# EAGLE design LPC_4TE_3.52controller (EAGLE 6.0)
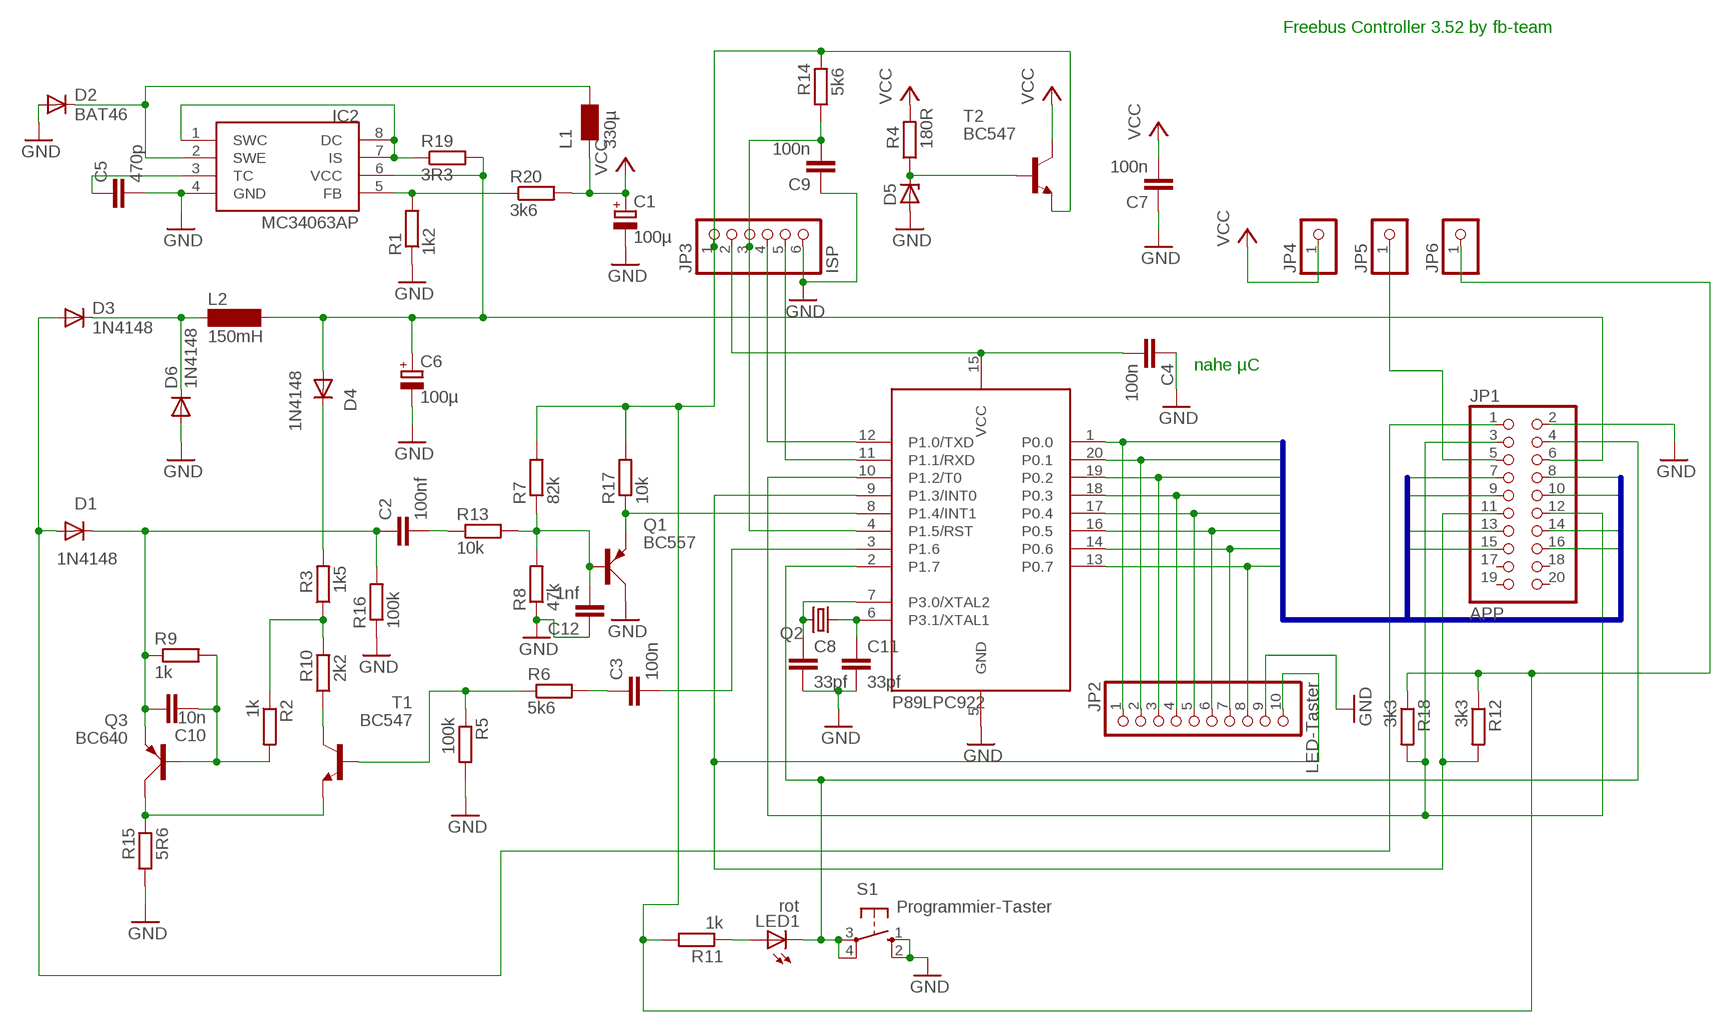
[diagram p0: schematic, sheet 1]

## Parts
C1  100µ  CPOL-EUE5-8.5  [E5-8,5]
C2  100nf  C-EU050-024X044  [C050-024X044]
C3  100n  C-EU050-024X044  [C050-024X044]
C4  100n  C-EU050-024X044  [C050-024X044]
C5  470p  C-EU025-024X044  [C025-024X044]
C6  100µ  CPOL-EUE5-8.5  [E5-8,5]
C7  100n  C-EU050-024X044  [C050-024X044]
C8  33pf  C-EUC1206  [C1206]
C9  100n  C-EU050-024X044  [C050-024X044]
C10  10n  C-EU050-024X044  [C050-024X044]
C11  33pf  C-EUC1206  [C1206]
C12  1nf  C-EU050-024X044  [C050-024X044]
D1  1N4148  1N4148DO35-7  [DO35-7]
D2  BAT46  DIODE-C1702-05  [C1702-05]
D3  1N4148  DIODE-D-2.5  [D-2.5]
D4  1N4148  1N4148DO35-10  [DO35-10]
D5  BZX85ZD-VL  [RAD2,5L]
D6  1N4148  DIODE-D-2.5  [D-2.5]
IC1  89LPC922FN  89LPC922  [DIL20]
IC2  MC34063AP  [DIL08]
JP1  APP  PINHD-2X10  [2X10]
JP2  LED-Taster  PINHD-1X10  [1X10]
JP3  ISP  PINHD-1X6  [1X06]
JP4  PINHD-1X1  [1X01]
JP5  PINHD-1X1  [1X01]
JP6  PINHD-1X1  [1X01]
L1  330µ  L_R85  [L_RAD_D8RM5]
L2  150mH  SD12-1000  [SD12_1000]
LED1  rot  LED3MM  [LED3MM]
Q1  BC557  [SOT54A]
Q2  CRYSTALHC49U70  [HC49U70]
Q3  BC640  [SOT54D]
R1  1k2  R-EU_0207/10  [0207/10]
R2  1k  R-EU_0207/7  [0207/7]
R3  1k5  R-EU_0207/7  [0207/7]
R4  180R  R-EU_0207/2V  [0207/2V]
R5  100k  R-EU_0207/2V  [0207/2V]
R6  5k6  R-EU_0207/7  [0207/7]
R7  82k  R-EU_0207/7  [0207/7]
R8  47k  R-EU_0207/7  [0207/7]
R9  1k  R-EU_0207/7  [0207/7]
R10  2k2  R-EU_0207/7  [0207/7]
R11  1k  R-EU_0207/10  [0207/10]
R12  3k3  R-EU_0207/10  [0207/10]
R13  10k  R-EU_0207/7  [0207/7]
R14  5k6  R-EU_0207/10  [0207/10]
R15  5R6  R-EU_0207/2V  [0207/2V]
R16  100k  R-EU_0207/7  [0207/7]
R17  10k  R-EU_0207/7  [0207/7]
R18  3k3  R-EU_0207/10  [0207/10]
R19  3R3  R-EU_0207/10  [0207/10]
R20  3k6  R-EU_0207/10  [0207/10]
S1  Programmier-Taster  10-XX  [B3F-10XX]
T1  BC547  [TO92]
T2  BC547  [TO92]

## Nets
/RESTET: C9.2 IC1.4(P1.5/RST) JP3.3 R14.1
DRAIN: C2.1 C10.1 D1.C Q3.E R9.1 R16.2
EIB_DC: C6.+ D4.A IC2.6(VCC) JP1.6 L2.2 R19.2
EIBIN: IC1.8(P1.4/INT1) Q1.E R17.1
GND: C1.- C4.1 C5.2 C6.- C7.1 C8.2 C9.1 C11.2 C12.1 D2.A D5.A D6.A IC1.5(GND) IC2.4(GND) JP1.2 JP2.9 JP3.6 Q1.C R1.1 R5.2 R8.1 R15.1 R16.1 S1.1(S) S1.2(S1)
INT0_TASTER: IC1.9(P1.3/INT0) JP1.11 JP2.10 R12.2
N$1: C3.1 R6.2
N$2: C2.2 R13.1
N$3: IC2.5(FB) R1.2 R20.1
N$4: IC2.1(SWC) IC2.7(IS) IC2.8(DC) R19.1
N$5: C3.2 IC1.3(P1.6)
N$6: R10.1 T1.3(C)
N$7: Q3.C R15.2 T1.1(E)
N$8: D3.C D6.C L2.1
N$9: D4.C R3.2
N$10: D2.C IC2.2(SWE) L1.1
N$11: R2.1 R3.1 R10.2
N$12: R5.1 R6.1 T1.2(B)
N$13: C5.1 IC2.3(TC)
N$14: C12.2 Q1.B R7.1 R8.2 R13.2
N$15: C10.2 Q3.B R2.2 R9.2
N$16: D1.A D3.A JP1.1
N$17: C11.1 IC1.6(P3.1/XTAL1) Q2.1
N$18: D5.C R4.1 T2.2(B)
N$19: C8.1 IC1.7(P3.0/XTAL2) Q2.2
N$20: JP1.5 JP5.1
N$29: IC1.12(P1.0/TXD) JP3.4
N$30: IC1.11(P1.1/RXD) JP3.5
N$41: LED1.A R11.1
P0.0: IC1.1(P0.0) JP1.7 JP2.1
P0.1: IC1.20(P0.1) JP1.8 JP2.2
P0.2: IC1.19(P0.2) JP1.9 JP2.3
P0.3: IC1.18(P0.3) JP1.10 JP2.4
P0.4: IC1.17(P0.4) JP1.13 JP2.5
P0.5: IC1.16(P0.5) JP1.14 JP2.6
P0.6: IC1.14(P0.6) JP1.15 JP2.7
P0.7: IC1.13(P0.7) JP1.16 JP2.8
PROG: IC1.2(P1.7) JP1.4 LED1.K(C) S1.3(P) S1.4(P1)
PWM: IC1.10(P1.2/T0) JP1.3 JP1.12 R18.2
VCC: C1.+ C7.2 JP4.1 L1.2 R4.2 R20.2 T2.3(C)
VCC_3V3: JP3.1 JP6.1 R7.2 R11.2 R12.1 R14.2 R17.2 R18.1 T2.1(E)
VCC_LPC: C4.2 IC1.15(VCC) JP3.2
Unconnected: JP1.17 JP1.18 JP1.19 JP1.20

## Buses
P0.[0..7]

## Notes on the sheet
- Freebus Controller 3.52 by fb-team
- nahe µC
- P89LPC922

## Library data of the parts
C1 C6 = rcl:CPOL-EU: POLARIZED CAPACITOR, European symbol
C2-C5 C7-C12 = rcl:C-EU: CAPACITOR, European symbol
D1 D4 = diode:1N4148: DIODE
D2 D3 D6 = diode:DIODE-: DIODE
D5 = diode:BZX85: Z DIODE
IC1 = micro-philips:89LPC922
IC2 = mc34063:MC34063
JP1 = pinhead:PINHD-2X10: PIN HEADER
JP2 = pinhead:PINHD-1X10: PIN HEADER
JP3 = pinhead:PINHD-1X6: PIN HEADER
JP4-JP6 = pinhead:PINHD-1X1: PIN HEADER
L1 = fbctrls1:L
L2 = inductor-neosid:SD12: INDUCTOR
LED1 = led:LED: LED
Q1 = transistor-small-signal:BC557: PNP TRANSISTOR
Q2 = crystal:CRYSTAL: CRYSTAL
Q3 = transistor-small-signal:BC640: PNP TRANSISTOR
R1-R20 = rcl:R-EU_: RESISTOR, European symbol
S1 = switch-omron:10-XX: OMRON SWITCH
T1 T2 = transistor:BC547: NPN TRANSISTOR

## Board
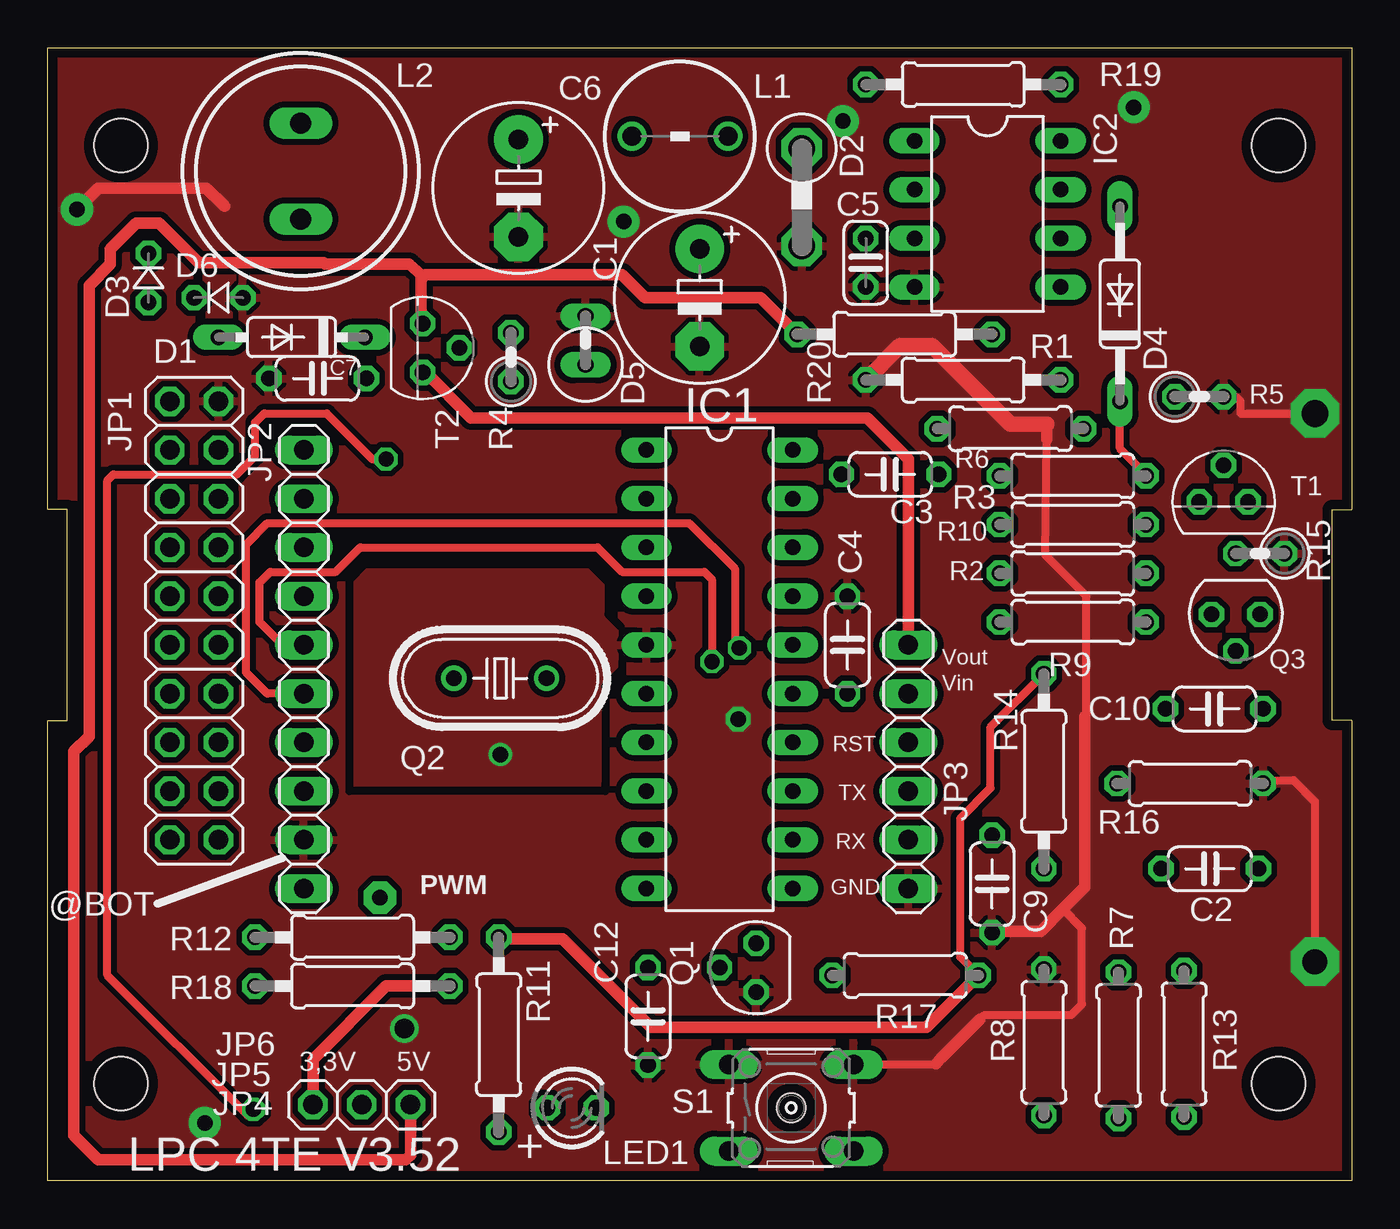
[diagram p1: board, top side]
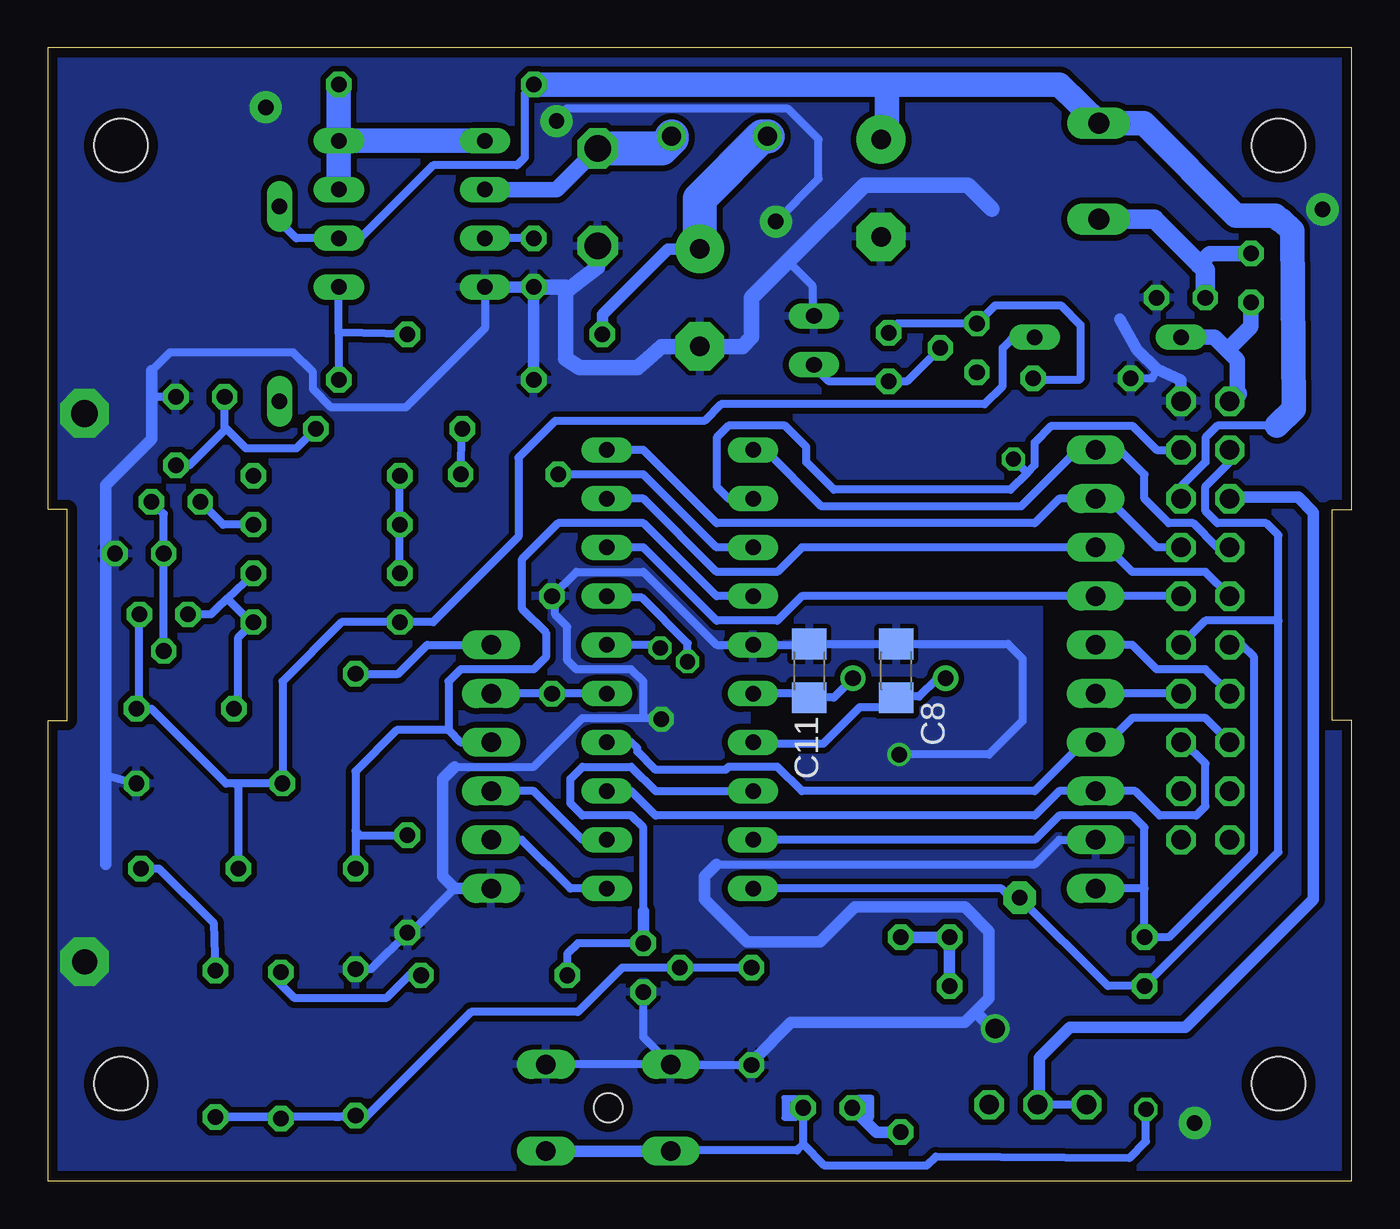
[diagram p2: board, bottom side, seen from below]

Size 67.94 x 59.05 mm. Coordinates in mm from the lower left corner, seen from the top.
Outline: 0,0 0,24 1,24 1,35 0,35 0,59.05 67.94,59.05 67.94,35 66.94,35 66.94,24 67.94,24 67.94,0 0,0
Copper layers (1*16): Top 0.035mm / dielectric 1.5mm / Bottom 0.035mm
Design rules "default *": minimum track width 10mil, minimum drill 24mil, track to track 12mil, track to pad 12mil, pad to pad 12mil, via to via 12mil, smd to smd 8mil, copper to edge 20mil, drill to drill 8mil, minimum pad ring 10mil, minimum via ring 8mil, stop-mask expansion 4mil, vias tented up to drill 0mil, thermal gap 10mil
Holes 2.8 mm at 3.81,53.98 64.14,53.98 64.14,5.08 3.81,5.08
Holes 1.5 mm at 38.73,3.81
tRestrict: 11 lines
bRestrict: 3 lines

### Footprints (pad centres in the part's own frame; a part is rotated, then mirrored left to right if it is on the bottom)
E5-8,5 = drill 1.016 pad 2.54 round: + -2.54,0 | drill 1.016 pad 2.54 octagon: - 2.54,0
C050-024X044 = drill 0.813 octagon: 1 -2.54,0; 2 2.54,0
C025-024X044 = drill 0.813 octagon: 1 -1.27,0; 2 1.27,0
C1206 = smd 1.6 x 1.8: 1 -1.4,0; 2 1.4,0
DO35-7 = drill 0.813 long: A 3.81,0; C -3.81,0
C1702-05 = drill 1.397 octagon: A 2.54,0; C -2.54,0
D-2.5 = drill 0.813 octagon: A 1.27,0; C -1.27,0
DO35-10 = drill 0.813 long: A 5.08,0; C -5.08,0
RAD2,5L = drill 0.813 long: A 1.27,0; C -1.27,0
DIL20 = drill 0.813 long: 1 -11.43,-3.81; 2 -8.89,-3.81; 3 -6.35,-3.81; 4 -3.81,-3.81; 5 -1.27,-3.81; 6 1.27,-3.81; 7 3.81,-3.81; 8 6.35,-3.81; 9 8.89,-3.81; 10 11.43,-3.81; 11 11.43,3.81; 12 8.89,3.81; 13 6.35,3.81; 14 3.81,3.81; 15 1.27,3.81; 16 -1.27,3.81; 17 -3.81,3.81; 18 -6.35,3.81; 19 -8.89,3.81; 20 -11.43,3.81
DIL08 = drill 0.813 long: 1 -3.81,-3.81; 2 -1.27,-3.81; 3 1.27,-3.81; 4 3.81,-3.81; 5 3.81,3.81; 6 1.27,3.81; 7 -1.27,3.81; 8 -3.81,3.81
2X10 = drill 1.016 octagon: 1 -11.43,-1.27; 2 -11.43,1.27; 3 -8.89,-1.27; 4 -8.89,1.27; 5 -6.35,-1.27; 6 -6.35,1.27; 7 -3.81,-1.27; 8 -3.81,1.27; 9 -1.27,-1.27; 10 -1.27,1.27; 11 1.27,-1.27; 12 1.27,1.27; 13 3.81,-1.27; 14 3.81,1.27; 15 6.35,-1.27; 16 6.35,1.27; 17 8.89,-1.27; 18 8.89,1.27; 19 11.43,-1.27; 20 11.43,1.27
1X10 = drill 1.016 long: 1 -11.43,0; 2 -8.89,0; 3 -6.35,0; 4 -3.81,0; 5 -1.27,0; 6 1.27,0; 7 3.81,0; 8 6.35,0; 9 8.89,0; 10 11.43,0
1X06 = drill 1.016 long: 1 -6.35,0; 2 -3.81,0; 3 -1.27,0; 4 1.27,0; 5 3.81,0; 6 6.35,0
1X01 = drill 1.016 octagon: 1 0,0
L_RAD_D8RM5 = drill 1 round: 1 -2.5,0; 2 2.5,0
SD12_1000 = drill 1.1 long: 1 -2.5,0; 2 2.5,0
LED3MM = drill 0.813 octagon: A -1.27,0; K 1.27,0
SOT54A = drill 0.813 octagon: B 0,1.905; C -1.27,0; E 1.27,0
HC49U70 = drill 0.813 round: 1 -2.413,0; 2 2.413,0
SOT54D = drill 0.813 octagon: B 1.27,0; C 0,1.905; E -1.27,0
0207/10 = drill 0.813 octagon: 1 -5.08,0; 2 5.08,0
0207/7 = drill 0.813 octagon: 1 -3.81,0; 2 3.81,0
0207/2V = drill 0.813 octagon: 1 -1.27,0; 2 1.27,0
B3F-10XX = drill 1.016 long: 1 -3.251,2.261; 2 3.251,2.261; 3 -3.251,-2.261; 4 3.251,-2.261
TO92 = drill 0.813 octagon: 1 1.27,0; 2 0,1.905; 3 -1.27,0

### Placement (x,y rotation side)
C1  33.97,46.04 270 top
C2  60.56,16.27 0 top
C3  43.89,36.83 180 top
C4  41.67,27.94 270 top
C5  42.62,47.86 270 top
C6  24.53,51.75 270 top
C7  14.05,41.83 0 top
C8  23.73,26.59 90 bottom
C9  49.21,15.48 90 top
C10  60.8,24.61 180 top
C11  28.26,26.59 90 bottom
C12  31.27,8.57 90 top
D1  12.7,43.97 180 top
D2  39.29,51.28 270 top
D3  5.24,47.07 270 top
D4  55.88,45.72 90 top
D5  28.02,43.81 90 top
D6  8.89,46.04 0 top
IC1  35,26.67 270 top
IC2  48.97,50.4 270 top
JP1  7.62,29.21 270 top
JP2  13.34,26.67 270 top
JP3  44.85,21.59 270 top
JP4  18.89,3.97 0 top
JP5  16.35,3.97 0 top
JP6  13.81,3.97 0 top
L1  32.94,54.45 180 top
L2  13.18,52.63 90 top
LED1  27.3,3.81 0 top
Q1  36.91,11.11 90 top
Q2  23.57,26.19 180 top
Q3  61.91,29.53 180 top
R1  47.7,41.75 0 top
R2  53.42,31.67 0 top
R3  53.42,36.75 0 top
R4  24.13,42.94 90 top
R5  60.01,40.88 0 top
R6  50.16,39.21 180 top
R7  55.8,7.06 90 top
R8  51.91,7.22 270 top
R9  53.42,29.13 0 top
R10  53.42,34.21 180 top
R11  23.5,7.62 90 top
R12  15.88,12.7 180 top
R13  59.21,7.14 270 top
R14  51.91,21.35 90 top
R15  63.18,32.7 180 top
R16  59.53,20.72 180 top
R17  44.69,10.72 0 top
R18  15.88,10.16 180 top
R19  47.7,57.15 180 top
R20  44.13,44.13 180 top
S1  38.73,3.81 0 top
T1  61.28,35.4 0 top
T2  19.53,43.42 270 top

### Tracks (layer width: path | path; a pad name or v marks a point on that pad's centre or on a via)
/RESTET
  Bottom 0.406: IC1.4 33.1,30.48 36.91,34.29 41.35,34.29 43.26,32.38 43.26,29.84 41.99,28.57 41.99,27.3 42.62,26.67 46.43,26.67 47.07,26.04 47.07,23.5 | JP3.3 46.43,22.86 47.07,23.5 | 51.91,18.26 51.91,21.35 49.77,23.5 47.07,23.5 | 51.91,18.26 R14.1 | C9.2 51.67,18.02 51.91,18.26
DRAIN
  Bottom 0.406: Q3.E 63.18,24.77 C10.1 62.55,24.61 58.66,20.72 58.18,20.72 | R9.1 47.86,29.13 43.42,33.58 43.42,37.7 41.51,39.61 33.73,39.61 32.86,40.48 19.13,40.48 18.18,41.43 18.18,43.42 17.38,44.21 16.75,44.21 D1.C | R9.1 | R16.2 58.18,20.72 | C2.1 58.02,20.56 58.18,20.72 | R9.1 52.63,29.13 55.72,26.04 R16.2 | R16.2
EIB_DC
  Bottom 0.406: JP1.6 8.89,36.2 7.62,37.47 7.62,38.73 6.99,39.37 3.89,39.37 | R19.2 43.1,56.67 43.1,53.82 43.1,53.34 43.5,52.94 47.86,52.94 51.67,49.13 IC2.6 55.01,49.13 55.88,50.01 D4.A | D4.A
  Bottom 1.27: 3.89,39.37 3.02,40.24 3.1,49.45 3.1,49.53 3.65,50.09 3.73,50.09 3.97,50.32 6.03,50.32 10.83,55.13 L2.2 15.24,57.15 24.21,57.15 | 24.21,57.15 R19.2 | C6.+ 24.21,54.61 24.21,57.15
EIBIN
  Bottom 0.406: IC1.8 36.27,20.32 37.54,21.59 40.08,21.59 40.72,20.95 40.72,19.68 40.08,19.05 37.54,19.05 36.91,18.41 36.91,13.89 | Q1.E 40.32,12.38 40.88,11.83 R17.1 | R17.1
  Bottom 0.61: 36.91,14.05 36.91,13.89 Q1.E
GND  (via drill 0.8, 0.8 pad 1.27, 0.8 pad 1.68, 1, 1.3 pad 2.54, 1.4 pad 2.54)
  Top 0.406: v66.04,40.01 62.15,40.01 62.15,40.64 61.91,40.88 R5.2 | 52.07,38.66 51.99,32.62 54.13,30.48 54.13,24.29 54.05,24.21 | v66.04,11.43 66.04,19.76 64.93,20.88 63.5,20.88 R16.1 | 48.58,8.41 48.82,8.65 53.34,8.65 53.9,9.21 53.9,13.18 52.9,14.17 | S1.2 46.23,6.07 46.55,6.39
  Top 0.61: 54.05,24.21 54.05,15.32 52.9,14.17 51.75,13.02 49.29,13.02 C9.1 | 52.07,38.66 52.07,39.45 | 48.58,8.41 46.55,6.39 46.28,6.11 | v1.51,50.64 2.62,51.75 8.26,51.75 9.21,50.8
  Top 0.813: 52.07,39.45 50.16,39.45 46.08,43.54 44.41,43.54 R1.1
  Bottom 0.406: 36.91,24.13 36.91,26.04 37.54,26.67 40.4,26.67 40.88,27.15 40.88,28.89 41.51,29.53 41.51,30.32 C4.1 | 36.91,24.13 40.08,24.13 42.62,21.59 46.75,21.59 | JP2.9 15.24,17.78 16.51,16.51 33.1,16.51 | C4.1 40.4,31.75 36.91,31.75 33.1,27.94 IC1.5 28.31,27.94 C11.2 C8.2 17.91,27.99 17.14,27.23 17.14,23.97 18.89,22.23 v23.57,22.23 | D5.A 28.1,45.09 28.1,46.67 29.37,47.94 30.16,47.15 | 62.55,40.88 R5.2 | 62.55,40.88 | R15.1 64.85,32.7 64.93,32.78 | Q1.C 36.91,7.5 S1.1 | S1.1 S1.2 | 46.75,15.24 49.05,12.94 C9.1 51.12,11.03 R8.1 | 64.93,16.51 64.93,20.95 64.77,21.11 R16.1 | 31.83,6.03 C12.1 | 31.83,6.03 35.24,6.03 35.32,6.11 | 35.32,6.11 35.24,6.19 | 31.11,6.35 31.51,6.35 31.83,6.03 | S1.1 35.36,6.07 35.32,6.11 | IC2.4 45.16,44.45 49.29,40.32 53.18,40.32 54.13,41.27 54.13,42.15 55.17,43.18 61.59,43.18 62.55,42.23 | C4.1 | v35.98,24.07 36.6,24.13 36.91,24.13 | C7.1 10.4,41.83 10.16,42.31 | 40.96,55.88 29.37,55.88 27.78,54.29 27.78,52.23 v30,50.01
  Bottom 0.61: JP3.6 46.75,15.24 47.39,15.88 47.39,20.95 46.75,21.59 | S1.1 35.48,6.27 35.56,6.35 | 33.1,16.51 33.73,15.88 33.73,14.68 31.51,12.46 27.7,12.46 25.88,14.29 20.16,14.29 18.89,13.02 18.89,9.53 19.61,8.81 | 31.11,6.35 29.21,8.26 20.16,8.26 19.61,8.81 | JP1.2 8.89,41.75 10.16,42.31 11.19,43.34 12.06,44.93 | IC2.4 C5.2 R1.1 | 62.55,42.23 62.55,40.88 62.55,38.66 64.93,36.27 64.93,32.78 64.93,16.51 | v18.57,7.94 18.34,7.54 19.61,8.81
  Bottom 0.813: 40.96,46.35 40.96,42.86 40.24,42.39 37.23,42.39 36.67,42.86 35.96,43.5 C1.- 31.75,43.5 31.27,43.97 31.27,46.04 29.37,47.94 25.4,51.91 20,51.91 18.73,50.64 | 40.96,46.35 40.96,46.59 C5.2 | D2.A 39.29,47.62 40.96,46.35
  other vias: 8.18,3.02 56.59,55.96 41.43,55.24
  pour Bottom: -0.16,0 0,59.05 67.94,59.05 67.94,0
  pour Top: -0.16,59.37 -0.16,-0.32 68.26,-0.32 68.26,59.21 0.32,59.21
INT0_TASTER
  Bottom 0.406: IC1.9 16.51,17.78 15.24,19.05 11.43,19.05 10.79,18.41 10.79,15.24 | JP1.11 5.71,27.94 5.08,27.3 5.08,17.14 9.53,12.7 R12.2 10.79,15.24 | 10.79,15.24 JP2.10
N$1
  Bottom 0.406: C3.1 R6.2
N$2
  Bottom 0.406: C2.2 62.15,16.27 59.29,13.41 R13.1 | C2.2
N$3
  Bottom 0.406: 52.78,44.13 R1.2 | 52.78,44.13 IC2.5 | R20.1 52.7,44.21 52.78,44.13
N$4
  Bottom 1.27: IC2.1 IC2.8 | IC2.8 IC2.7 | IC2.8 R19.1
N$5
  Bottom 0.406: IC1.3 33.1,33.02 36.91,36.83 C3.2
N$6
  Bottom 0.406: R10.1 58.82,34.21 T1.3
N$7
  Bottom 0.406: Q3.C R15.2 61.91,34.77 T1.1
N$8
  Bottom 0.813: D3.C 7.38,48.34 7.94,47.78
  Bottom 1.016: D6.C 7.62,47.47 7.94,47.78 10.28,50.13 L2.1
N$9
  Top 0.406: R3.2 57.23,36.83 55.88,38.18 D4.C | D4.C
N$10
  Bottom 0.813: IC2.2 41.43,51.67 D2.C
  Bottom 1.778: L1.1 35.44,54.33 35.96,53.82 D2.C
N$11
  Bottom 0.406: R10.2 R3.1 | R10.2 | R2.1 R10.2 | R2.1
N$12
  Bottom 0.406: 58.66,39.21 57.63,38.18 55.01,38.18 R6.1 | 58.66,39.21 58.74,39.29 R5.1 | R5.1 | T1.2 60.56,37.31 58.66,39.21
N$13
  Bottom 0.406: C5.1 IC2.3
N$14
  Bottom 0.406: R7.1 56.28,3.33 R13.2 52.94,3.33 R8.2 52.78,3.33 51.36,3.33 45.88,8.81 40.32,8.81 38.02,11.11 Q1.B C12.2 | C12.2
N$15
  Bottom 0.406: Q3.B 59.45,29.53 59.17,29.8 58.6,30.36 | 58.6,30.36 R2.2 | C10.2 58.02,24.84 58.02,28.34 R9.2 57.37,29.13 58.6,30.36
N$16
  Bottom 0.61: JP1.1 6.27,40.72
  Bottom 0.813: 5.95,41.04 5.95,42.78 6.47,43.3 | 6.47,43.3 7.14,43.97 D1.A | D3.A 5.24,44.53 6.47,43.3
  Bottom 1.016: 6.27,40.72 5.95,41.04
N$17
  Bottom 0.406: IC1.6 28.47,25.4 C11.1 26.99,25.19 Q2.1
N$18
  Bottom 0.406: D5.C 28.02,42.47 27.23,41.67 R4.1 23.18,41.67 T2.2
N$19
  Bottom 0.406: Q2.2 21.59,26.19 22.54,25.24 23.68,25.24 C8.1 23.94,25.19 24.45,24.69 25.64,24.69 27.54,22.78 31.11,22.78 IC1.7
N$20
  Bottom 0.61: JP5.1 16.27,4.05 16.27,6.43 14.68,8.02 8.65,8.02 1.98,14.68 1.98,34.85 2.78,35.64 6.27,35.64 JP1.5
N$29
  Bottom 0.406: IC1.12 40.08,17.78 42.62,20.32 JP3.4
N$30
  Bottom 0.406: IC1.11 40.72,15.24 43.26,17.78 JP3.5
N$41
  Bottom 0.254: 25.66,4.32 25.68,4.32 25.72,4.36 25.02,4.36 25,4.34 25,3.33 25.06,3.27 25.71,3.27 25.72,3.28 25.72,3.3 | 25.72,3.3 25.48,3.54 25.48,4.13 25.45,4.16 25.23,4.16 25.22,4.17 25.22,3.47 25.34,3.47 25.36,3.48 25.36,4.06 25.36,4.07 | 25.72,3.3 25.72,3.31 25.63,3.4
  Bottom 0.61: R11.1 24.77,2.54 25.63,3.4 LED1.A
P0.0
  Bottom 0.406: JP1.7 6.99,33.02 8.26,34.29 9.53,34.29 10.79,35.56 10.79,36.83 12.06,38.1 JP2.1 14.29,38.1 17.22,35.16 27.62,35.16 30.56,38.1 IC1.1
P0.1
  Bottom 0.406: IC1.20 36.91,38.1 33.1,34.29 16.51,34.29 15.24,35.56 JP2.2 12.7,35.56 10.16,33.02 JP1.8
P0.2
  Bottom 0.406: JP1.9 7.62,31.75 11.43,31.75 12.7,33.02 JP2.3 28.65,33.02 29.92,31.75 33.1,31.75 36.91,35.56 IC1.19
P0.3
  Bottom 0.406: IC1.18 36.91,33.02 33.1,29.21 29.92,29.21 28.65,30.48 JP2.4 JP1.10
P0.4  (via drill 0.8)
  Top 0.406: JP2.5 12.22,27.94 11.03,29.13 11.03,31.19 11.59,31.75 15,31.75 16.27,33.02 28.65,33.02 29.92,31.75 34.21,31.75 34.61,31.35 v34.61,27.07
  Bottom 0.406: JP1.13 7.62,26.67 10.16,26.67 11.43,27.94 JP2.5 | v34.61,27.07 34.61,28.02 36.99,30.4 38.73,30.4 IC1.17
P0.5  (via drill 0.8)
  Top 0.406: JP2.6 11.43,25.4 10.32,26.51 10.32,33.18 11.43,34.29 33.42,34.29 35.8,31.91 35.8,28.02 v36.04,27.78
  Bottom 0.406: JP1.14 JP2.6 | v36.04,27.78 36.27,27.78 36.43,27.94 IC1.16
P0.6
  Bottom 0.406: JP1.15 7.62,24.13 11.43,24.13 12.7,22.86 JP2.7 13.97,22.86 16.51,20.32 28.65,20.32 29.92,21.59 32.46,21.59 32.62,21.43 36.27,21.43 | IC1.14 37.54,22.86 37.23,22.54 37.23,22.38 36.27,21.43 | 36.27,21.43
P0.7
  Bottom 0.406: IC1.13 37.54,20.32 36.27,19.05 16.51,19.05 15.24,20.32 JP2.8 11.27,20.32 10,19.05 8.1,19.05 7.62,19.53 7.62,21.75 8.73,22.86 JP1.16
PROG  (via drill 0.8)
  Top 0.406: v17.62,37.62 16.91,37.62 14.53,40.01 11.27,40.01 10.79,39.53 10.79,37.78 9.84,36.83 3.41,36.83 3.1,36.51 3.1,10.72 10.4,3.41 v10.72,3.73
  Bottom 0.254: 29.21,4.24 29.37,4.24 29.37,3.44 29.02,3.25 28.96,3.25 28.96,3.26 29.44,3.26 29.59,3.27 29.59,4.34 28.94,4.34 28.94,4.17 LED1.K
  Bottom 0.406: JP1.4 10.16,38.1 11.43,39.37 15.64,39.37 16.51,38.5 16.51,37.31 16.91,36.91 | IC1.2 32.46,35.56 33.1,36.2 33.1,38.73 32.46,39.37 29.53,39.37 28.42,38.26 28.42,37.47 26.99,36.04 17.78,36.04 16.91,36.91 | 28.57,1.91 LED1.K | 28.57,1.91 28.89,1.59 35.45,1.59 S1.3 | v17.62,37.62 16.91,36.91 | v10.72,3.73 10.72,2.06 11.59,1.19 21.67,1.27 22.15,0.79 27.46,0.79 28.57,1.91
  Bottom 0.61: 35.56,1.55 S1.3 34.57,1.55 | 35.56,1.55 S1.4 | 35.56,1.55 35.56,1.27
PWM  (via drill 0.8 pad 1.68)
  Bottom 0.406: v17.3,14.76 17.78,15.24 | v17.3,14.76 17.78,14.76 18.26,15.24 IC1.10 | 3.81,29.21 3.81,17.14 R18.2 12.7,10.16 v17.3,14.76 | 3.81,29.21 7.62,29.21 JP1.12 | JP1.3 6.35,37.47 7.62,36.2 7.62,34.92 6.99,34.29 4.45,34.29 3.81,33.66 3.81,29.21
VCC
  Top 0.61: JP4.1 18.89,1.35 18.65,1.11 2.62,1.11 1.35,2.38 1.35,22.38 2.14,23.18 2.14,46.67 3.25,47.78 3.25,48.58 4.6,49.93 5.79,49.93 7.86,47.86 14.37,47.86 14.45,47.78 16.67,47.78 18.81,47.78 19.45,47.23 19.45,46.99 | 19.45,46.99 19.45,44.77 T2.3 | R20.2 37.15,46.04 31.11,46.04 29.92,47.23 19.68,47.23 19.45,46.99
  Bottom 0.406: R4.2 23.65,44.69 T2.3 18.57,45.64 15.16,45.64 14.13,44.61 14.13,41.83 14.21,41.75 16.51,41.75 C7.2
  Bottom 0.61: C1.+ 35.64,48.58 39.05,45.16 R20.2
  Bottom 1.778: L1.2 30.72,54.45 33.97,51.2 C1.+ | C1.+
VCC_3V3
  Top 0.406: R17.2 47.55,11.67 47.55,18.89 49.13,20.48 49.13,23.65 R14.2
  Top 0.61: JP6.1 13.81,6.35 17.62,10.16 R18.1 | T2.1 19.68,42.15 22.07,39.77 42.7,39.77 44.85,37.62 JP3.1 | R11.2 23.57,12.62 26.83,12.62 31.43,8.02 45.8,8.02 R17.2
  Bottom 0.406: JP6.1 16.27,3.97 | R7.2 56.2,10.64 55.09,9.53 50.32,9.53 49.13,10.72 R17.2 | JP3.1 48.18,27.94 49.69,26.43 R14.2
  Bottom 0.61: R18.1 R12.1 R11.2
VCC_LPC
  Bottom 0.406: IC1.15 C4.2 | C4.2 | C4.2 JP3.2 | JP3.2

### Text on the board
tPlace: Vout | Vin | RST | TX | RX | @BOT | PWM | GND | 3,3V | 5V | +
tNames: LPC 4TE V3.52
tValues: auf Lötseite:
